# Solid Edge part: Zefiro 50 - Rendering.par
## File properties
Title: Zefiro 50
Author: DESYS
Template: Normal.par
Last saved by: i.fialdini
Revision: 34
Application: Solid Edge
Tipo di contenuto documento: 0
Precisione: 0.990
Document Number: 8207
Revision: 0
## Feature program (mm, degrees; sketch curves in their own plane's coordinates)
boolean "unnamed Boolean 1"
fillet "Rotondo_1" radius 5
fillet "Rotondo_4" radius 3
fillet "Rotondo_2" radius 50
fillet "Rotondo_5" radius 10
fillet "Rotondo_6" radius 15  VertexRadius1 = 15 mm; VertexRadius2 = 15 mm; VertexRadius3 = 99 mm; VertexRadius4 = 99 mm
lofted protrusion "unnamed LoftedProtrusion 1"
sketch for "unnamed Cutout 1" plane through (0, 0, 0) normal (1, 0, 0) x-axis (0, 1, 0)
  arc centre (0, 403.1295) radius 473.8295 from (-249, 0) to (249, 0) ccw
extrude "unnamed Cutout 1" cut through
thinwall "unnamed Thinwall 1"
sketch for "ExtrudedProtrusion_1" plane through (0, 0, -166) normal (0, 0, -1) x-axis (0, 1, 0)
extrude "ExtrudedProtrusion_1" add finite 20 along +normal
sketch for "ExtrudedCutout_2" plane through (0, 0, -186) normal (0, 0, -1) x-axis (0, 1, 0)
  bspline degree 3 poles (78.5, 0) (78.5, 4.3484) (77.9677, 8.9771) (75.4059, 18.625) (73.3678, 23.6507) (68.871, 31.1661) (67.1349, 33.6629) (63.1633, 38.5563) (60.9279, 40.953) (55.9699, 45.5444) (53.2474, 47.7391) (47.3673, 51.8237) (44.2097, 53.7136) (37.5532, 57.0996) (34.0537, 58.5961) (26.8352, 61.1329) (23.1161, 62.1734) (15.5949, 63.7732) (11.7927, 64.3327) (4.2395, 64.9813) (0.4885, 65.0705) (-10.5195, 64.6996) (-17.5064, 63.59) (-30.1906, 60.2077) (-35.8925, 57.9453) (-45.8726, 52.8699) (-50.8014, 49.7202) (-59.9157, 42.1889) (-64.091, 37.8048) (-71.0454, 28.0794) (-73.8151, 22.7419) (-77.5432, 11.6018) (-78.5017, 5.7991) (-78.5017, -5.7991) (-77.5432, -11.6018) (-73.8151, -22.7419) (-71.0454, -28.0794) (-64.091, -37.8048) (-59.9157, -42.1889) (-50.8014, -49.7202) (-45.8726, -52.8699) (-35.8925, -57.9453) (-30.1906, -60.2077) (-17.5064, -63.59) (-10.5195, -64.6996) (0.4885, -65.0705) (4.2395, -64.9813) (11.7927, -64.3327) (15.5949, -63.7732) (23.1161, -62.1734) (26.8352, -61.1329) (34.0537, -58.5961) (37.5532, -57.0996) (44.2097, -53.7136) (47.3673, -51.8237) (53.2474, -47.7391) (55.9699, -45.5444) (60.9279, -40.953) (63.1633, -38.5563) (67.1349, -33.6629) (68.871, -31.1661) (73.3678, -23.6507) (75.4059, -18.625) (77.9677, -8.9771) (78.5, -4.3477) (78.5, 0) knots 0 0.0417 0.0833 0.1042 0.125 0.1458 0.1667 0.1875 0.2083 0.2292 0.25 0.2917 0.3333 0.375 0.4167 0.4583 0.5 0.5417 0.5833 0.625 0.6667 0.7083 0.75 0.7708 0.7917 0.8125 0.8333 0.8542 0.875 0.8958 0.9167 0.9583 1 multiplicities 4 2 2 2 2 2 2 2 2 2 2 2 2 2 2 2 2 2 2 2 2 2 2 2 2 2 2 2 2 2 2 2 4
extrude "ExtrudedCutout_2" cut finite 15 along -normal
sketch for "ExtrudedProtrusion_2" plane through (-0.0026, 0, -171) normal (0, 0, -1) x-axis (0, 1, 0)
  circle centre (0, 0.0026) radius 32.5
extrude "ExtrudedProtrusion_2" add finite 15 along +normal
sketch for "Foro_1" plane through (0, 0, -186) normal (0, 0, -1) x-axis (0, 1, 0)
  hole centre (0, 0) bore radius 25
hole "Foro_1" diameter 50 through
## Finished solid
Body 1: sheet body, 1 face, 2 edges, 0 vertices.
  Faces by surface: spline 1
  Edges by curve: circle 1, intersection 1
Body 2: solid body, 21 faces, 32 edges, 13 vertices.
  Faces by surface: spline 6, blend 4, cylinder 3, plane 3, swept 3, torus 2
  Edges by curve: curve on surface 12, intersection 12, circle 5, ellipse 2, spline 1
Bounding box of the edges (mm; curved faces can reach further): 362.139 x 491.344 x 179.631, from (-180.9358, -245.6598, -186) to (181.203, 245.6843, -6.3692).
Cylindrical faces by radius (mm): R25 x1, R32.5 x1, R473.8295 x1
Toroidal faces (ring radius, tube radius in mm): R29.5 r3 x1, R35.5 r3 x1
Planar faces by outward normal: -z 3
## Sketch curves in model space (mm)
arc centre (0, -25, 69.0304) radius 225.0304 from (0, -236.6669, -7.3619) through (0, -148.8985, -118.8202) to (0, -25, -156)
arc centre (0, 25, 69.0304) radius 225.0304 from (0, 236.6669, -7.3619) through (0, 148.8985, -118.8202) to (0, 25, -156)
arc centre (25, 0, 14.8528) radius 170.8528 from (25, 0, -156) through (110.3632, 0, -133.1465) to (172.8898, 0, -70.7)
arc centre (-25, 0, 14.8528) radius 170.8528 from (-172.8898, 0, -70.7) through (-110.3632, 0, -133.1465) to (-25, 0, -156)
arc centre (39.297, 0, -28.8317) radius 150 from (186.5, 0, 0) through (170.233, 0, -102.0148) to (100, 0, -166)
arc centre (-39.297, 0, -28.8317) radius 150 from (-186.5, 0, 0) through (-170.233, 0, -102.0148) to (-100, 0, -166)
arc centre (0, 6.2657, 59.8336) radius 250 from (0, 249, 0) through (0, 199.9368, -98.2534) to (0, 113.5, -166)
arc centre (0, -6.2657, 59.8336) radius 250 from (0, -249, 0) through (0, -199.9368, -98.2534) to (0, -113.5, -166)
ellipse centre (0, 0, -166) radii 113.5, 100
ellipse centre (0, 0, 0) radii 249, 186.5
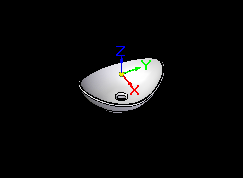
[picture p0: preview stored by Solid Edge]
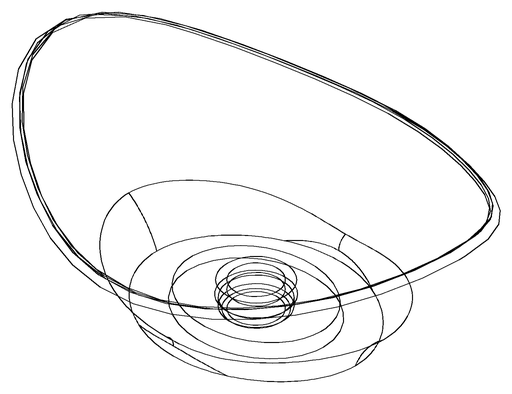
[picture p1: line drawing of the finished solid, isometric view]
